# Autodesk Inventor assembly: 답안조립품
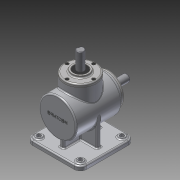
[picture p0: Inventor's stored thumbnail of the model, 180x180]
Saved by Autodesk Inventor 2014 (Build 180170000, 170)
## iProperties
Created: 2015-07
Part Number: 답안조립품
Document SubType Name: Assembly
Designer: Owner
Author: Owner
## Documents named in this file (14)
- C:\Documents and Settings\Owner\바탕 화면\450705V1001\답안조립품.iam
- C:\Documents and Settings\Owner\바탕 화면\450705V1001\1-본체.ipt
- C:\Documents and Settings\Owner\바탕 화면\450705V1001\베어링 6203.ipt
- C:\Documents and Settings\Owner\바탕 화면\450705V1001\커버.ipt
- C:\Documents and Settings\Owner\바탕 화면\450705V1001\서브 축.ipt
- 서브 축.ipt
- C:\Documents and Settings\Owner\바탕 화면\450705V1001\메인 축.ipt
- 메인 축.ipt
- C:\Documents and Settings\Owner\바탕 화면\450705V1001\키 4x4.ipt
- C:\Documents and Settings\Owner\바탕 화면\450705V1001\키 5x5.ipt
- C:\Documents and Settings\Owner\바탕 화면\450705V1001\메인 베벨기어.ipt
- C:\Documents and Settings\Owner\바탕 화면\450705V1001\서브 베벨기어.ipt
- C:\Documents and Settings\Owner\바탕 화면\450705V1001\오일실.ipt
- C:\Documents and Settings\Owner\바탕 화면\450705V1001\M4.ipt
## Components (9 placed, 2 different names)
1. 1-본체:1
2. M4:1
3. M4:3
4. M4:4
5. M4:5
6. M4:2
7. M4:6
8. M4:7
9. M4:8
